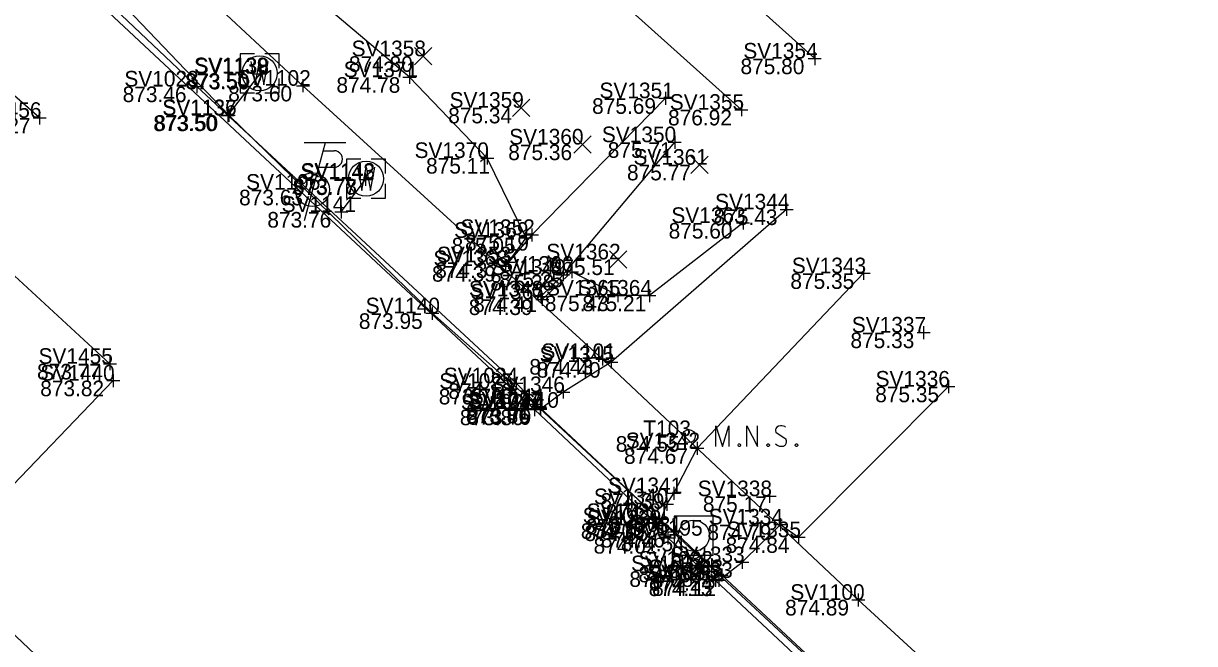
# Model space of a CAD drawing. Extents: x 1480001 to 1480402, y 379235 to 379603.
# Drawn here: x 1480133.3 to 1480223.3, y 379434.1 to 379481.8 of the extents above; entities that cross this region are included whole.
import ezdxf

# ---------------------------------------------------------------- set-up
doc = ezdxf.new("R2010")
doc.units = 0
for name, color, linetype in [('BD_X_Building', 7, 'Continuous'), ('BD_X_Porch_or_Deck', 7, 'Continuous'), ('PM_P_CL_Double_Solid', 7, 'Continuous'), ('PM_X_Lane_Line', 7, 'Continuous'), ('PM_X_Stop_Line', 7, 'Continuous'), ('PV_X_Curb', 7, 'Continuous'), ('PV_X_Driveway', 7, 'Continuous'), ('PV_X_Walk', 7, 'Continuous'), ('SG_X_Poles', 7, 'Continuous'), ('SV_P_Control_Cells_Set', 7, 'Continuous'), ('SV_X_Random_Point', 7, 'Continuous'), ('SV_X_Shot_Marker', 7, 'Continuous'), ('SV_X_Text_Elevation', 7, 'Continuous'), ('SV_X_Text_Name', 7, 'Continuous'), ('SV_X_Top_of_Bank', 7, 'Continuous'), ('UT_X_Misc_Cells', 7, 'Continuous'), ('UT_X_Water', 7, 'Continuous'), ('UT_X_Water_Cells', 7, 'Continuous')]:
    doc.layers.add(name, color=color, linetype=linetype)

msp = doc.modelspace()

# ---------------------------------------------------------------- linework, layer by layer
at = {"layer": 'BD_X_Building'}
msp.add_line((1480194.12, 379479.058), (1480181.546, 379490.377), dxfattribs=at)
at = {"layer": 'BD_X_Porch_or_Deck'}
msp.add_line((1480188.477, 379475.121), (1480178.147, 379484.41), dxfattribs=at)
at = {"layer": 'PM_P_CL_Double_Solid'}
msp.add_lwpolyline([(1480030.312, 379558.368), (1480048.994, 379540.544), (1480068.184, 379522.458), (1480086.697, 379505.162), (1480104.247, 379488.61), (1480122.276, 379471.896), (1480139.96, 379455.601)], dxfattribs=at)
at = {"layer": 'PM_X_Lane_Line'}
msp.add_line((1480134.548, 379474.499), (1480127.117, 379481.028), dxfattribs=at)
at = {"layer": 'PM_X_Stop_Line'}
msp.add_line((1480127.237, 379440.807), (1480140.21, 379454.309), dxfattribs=at)
at = {"layer": 'PV_X_Curb'}
for points in [[(1480042.95, 379573.802), (1480051.182, 379566.018), (1480067.383, 379550.834), (1480087.586, 379531.809), (1480105.067, 379515.41), (1480105.589, 379514.887), (1480115.079, 379506.297), (1480116.303, 379505.052), (1480118.53, 379502.967), (1480120.902, 379500.821), (1480138.714, 379483.703), (1480170.84, 379453.681), (1480172.574, 379452.083), (1480181.867, 379443.345), (1480182.839, 379442.217), (1480185.607, 379439.661), (1480186.493, 379438.955), (1480206.919, 379419.855)], [(1480043.308, 379574.086), (1480051.435, 379566.534), (1480067.64, 379551.083), (1480087.827, 379532.141), (1480105.189, 379515.816), (1480105.937, 379515.205), (1480115.287, 379506.588), (1480116.588, 379505.377), (1480116.999, 379505.563), (1480121.373, 379501.34), (1480121.053, 379501.135), (1480146.64, 379476.909), (1480171.177, 379454.102), (1480173.021, 379452.229), (1480182.175, 379443.675), (1480183.379, 379442.683), (1480186.184, 379440.013), (1480186.975, 379439.363), (1480207.407, 379420.301)], [(1480135.19, 379432.332), (1480118.45, 379448.16), (1480110.152, 379455.954), (1480109.273, 379456.61), (1480100.92, 379464.722), (1480096.044, 379469.27), (1480093.779, 379471.437), (1480091.422, 379473.761), (1480089.145, 379475.876), (1480069.411, 379494.504), (1480056.455, 379506.379), (1480055.435, 379507.417), (1480042.302, 379520.019), (1480041.64, 379520.833), (1480030.984, 379530.729), (1480016.059, 379544.67)]]:
    msp.add_lwpolyline(points, dxfattribs=at)
at = {"layer": 'PV_X_Driveway'}
for points in [[(1480191.959, 379467.465), (1480178.482, 379455.738), (1480174.79, 379453.425), (1480173.043, 379452.118)], [(1480182.148, 379443.183), (1480182.758, 379444.811), (1480183.297, 379445.659), (1480185.095, 379449.116), (1480197.866, 379462.558)], [(1480186.755, 379438.964), (1480188.543, 379440.354), (1480191.477, 379443.253), (1480192.87, 379442.276), (1480204.388, 379453.849)]]:
    msp.add_lwpolyline(points, dxfattribs=at)
at = {"layer": 'PV_X_Walk'}
for points in [[(1480235.613, 379401.335), (1480215.341, 379421.047), (1480197.466, 379437.463), (1480177.803, 379455.97), (1480154.79, 379476.967), (1480132.747, 379497.48), (1480113.376, 379516.728), (1480110.754, 379519.04), (1480109.877, 379518.336), (1480091.944, 379535.267), (1480093.027, 379536.619), (1480090.219, 379539.243), (1480090.463, 379539.725), (1480084.681, 379544.882), (1480083.843, 379544.144), (1480066.818, 379560.524), (1480045.662, 379580.046)], [(1480182.64, 379476.009), (1480172.384, 379465.5), (1480170.586, 379463.4)], [(1480173.058, 379460.776), (1480174.782, 379462.443), (1480183.362, 379472.63)]]:
    msp.add_lwpolyline(points, dxfattribs=at)
at = {"layer": 'SG_X_Poles'}
msp.add_lwpolyline([(1480183.322, 379440.895), (1480186.322, 379440.895), (1480186.322, 379443.895), (1480183.322, 379443.895)], close=True, dxfattribs=at)
msp.add_circle((1480184.822, 379442.395), 1.2, dxfattribs=at)
at = {"layer": 'SV_P_Control_Cells_Set'}
for points in [[(1480186.529, 379449.245), (1480186.529, 379450.845), (1480187.036, 379449.245), (1480187.521, 379450.845), (1480187.521, 379449.245)], [(1480188.899, 379449.245), (1480188.899, 379450.845), (1480189.726, 379449.245), (1480189.726, 379450.845)], [(1480191.876, 379450.732), (1480191.854, 379450.757), (1480191.82, 379450.782), (1480191.721, 379450.82), (1480191.6, 379450.845), (1480191.512, 379450.845), (1480191.479, 379450.845), (1480191.335, 379450.808), (1480191.214, 379450.732), (1480191.137, 379450.631), (1480191.115, 379450.53), (1480191.115, 379450.455), (1480191.137, 379450.354), (1480191.225, 379450.266), (1480191.832, 379449.888), (1480191.887, 379449.838), (1480191.909, 379449.787), (1480191.931, 379449.712), (1480191.931, 379449.636), (1480191.92, 379449.56), (1480191.909, 379449.51), (1480191.887, 379449.447), (1480191.865, 379449.397), (1480191.842, 379449.359), (1480191.809, 379449.321), (1480191.776, 379449.296), (1480191.732, 379449.271), (1480191.699, 379449.258), (1480191.6, 379449.245), (1480191.446, 379449.245), (1480191.347, 379449.271), (1480191.203, 379449.359), (1480191.115, 379449.434)], [(1480188.293, 379449.46), (1480188.348, 379449.46), (1480188.381, 379449.434), (1480188.414, 379449.384), (1480188.414, 379449.321), (1480188.381, 379449.271), (1480188.348, 379449.245), (1480188.293, 379449.245), (1480188.26, 379449.271), (1480188.227, 379449.321), (1480188.227, 379449.384), (1480188.26, 379449.434), (1480188.293, 379449.46)], [(1480190.509, 379449.46), (1480190.564, 379449.46), (1480190.597, 379449.434), (1480190.63, 379449.384), (1480190.63, 379449.321), (1480190.597, 379449.271), (1480190.564, 379449.245), (1480190.509, 379449.245), (1480190.476, 379449.271), (1480190.443, 379449.321), (1480190.443, 379449.384), (1480190.476, 379449.434), (1480190.509, 379449.46)], [(1480192.691, 379449.46), (1480192.746, 379449.46), (1480192.78, 379449.434), (1480192.812, 379449.384), (1480192.812, 379449.321), (1480192.78, 379449.271), (1480192.746, 379449.245), (1480192.691, 379449.245), (1480192.658, 379449.271), (1480192.625, 379449.321), (1480192.625, 379449.384), (1480192.658, 379449.434), (1480192.691, 379449.46)]]:
    msp.add_lwpolyline(points, dxfattribs=at)
msp.add_circle((1480184.44, 379450.045), 0.497, dxfattribs=at)
at = {"layer": 'SV_X_Random_Point'}
for p, q in [((1480163.369, 379478.57), (1480164.703, 379479.905)), ((1480163.369, 379479.905), (1480164.703, 379478.57)), ((1480170.896, 379474.613), (1480172.23, 379475.948)), ((1480170.896, 379475.948), (1480172.23, 379474.613)), ((1480175.594, 379471.785), (1480176.928, 379473.12)), ((1480175.594, 379473.12), (1480176.928, 379471.785)), ((1480184.606, 379470.232), (1480185.94, 379471.567)), ((1480184.606, 379471.567), (1480185.94, 379470.232)), ((1480178.334, 379462.956), (1480179.668, 379464.291)), ((1480178.334, 379464.291), (1480179.668, 379462.956))]:
    msp.add_line(p, q, dxfattribs=at)
at = {"layer": 'SV_X_Shot_Marker'}
for p, q in [((1480194.12, 379479.558), (1480194.12, 379478.558)), ((1480151.509, 379478.389), (1480151.509, 379477.389)), ((1480193.62, 379479.058), (1480194.62, 379479.058)), ((1480194.12, 379479.058), (1480194.12, 379479.058)), ((1480151.009, 379477.889), (1480152.009, 379477.889)), ((1480151.509, 379477.889), (1480151.509, 379477.889)), ((1480154.79, 379477.467), (1480154.79, 379476.467)), ((1480162.466, 379477.627), (1480163.466, 379477.627)), ((1480162.966, 379478.127), (1480162.966, 379477.127)), ((1480162.966, 379477.627), (1480162.966, 379477.627)), ((1480146.14, 379476.909), (1480147.14, 379476.909)), ((1480146.64, 379477.409), (1480146.64, 379476.409)), ((1480146.64, 379476.909), (1480146.64, 379476.909)), ((1480154.29, 379476.967), (1480155.29, 379476.967)), ((1480154.79, 379476.967), (1480154.79, 379476.967)), ((1480182.14, 379476.009), (1480183.14, 379476.009)), ((1480182.64, 379476.509), (1480182.64, 379475.509)), ((1480182.64, 379476.009), (1480182.64, 379476.009)), ((1480134.548, 379474.999), (1480134.548, 379473.999)), ((1480149.013, 379475.18), (1480149.013, 379474.18)), ((1480149.088, 379475.208), (1480149.088, 379474.208)), ((1480187.977, 379475.121), (1480188.977, 379475.121)), ((1480188.477, 379475.621), (1480188.477, 379474.621)), ((1480188.477, 379475.121), (1480188.477, 379475.121)), ((1480134.048, 379474.499), (1480135.048, 379474.499)), ((1480134.548, 379474.499), (1480134.548, 379474.499)), ((1480148.513, 379474.68), (1480149.513, 379474.68)), ((1480148.588, 379474.708), (1480149.588, 379474.708)), ((1480149.013, 379474.68), (1480149.013, 379474.68)), ((1480149.088, 379474.708), (1480149.088, 379474.708)), ((1480183.362, 379473.13), (1480183.362, 379472.13)), ((1480182.862, 379472.63), (1480183.862, 379472.63)), ((1480183.362, 379472.63), (1480183.362, 379472.63)), ((1480168.447, 379471.416), (1480169.447, 379471.416)), ((1480168.947, 379471.916), (1480168.947, 379470.916)), ((1480168.947, 379471.416), (1480168.947, 379471.416)), ((1480159.603, 379470.273), (1480159.603, 379469.273)), ((1480159.103, 379469.773), (1480160.103, 379469.773)), ((1480159.603, 379469.773), (1480159.603, 379469.773)), ((1480157.731, 379467.768), (1480157.731, 379466.768)), ((1480191.959, 379467.965), (1480191.959, 379466.965)), ((1480157.231, 379467.268), (1480158.231, 379467.268)), ((1480157.731, 379467.268), (1480157.731, 379467.268)), ((1480188.616, 379466.924), (1480188.616, 379465.924)), ((1480191.459, 379467.465), (1480192.459, 379467.465)), ((1480191.959, 379467.465), (1480191.959, 379467.465)), ((1480171.936, 379465.783), (1480171.936, 379464.783)), ((1480172.384, 379466), (1480172.384, 379465)), ((1480188.116, 379466.424), (1480189.116, 379466.424)), ((1480188.616, 379466.424), (1480188.616, 379466.424)), ((1480171.436, 379465.283), (1480172.436, 379465.283)), ((1480171.884, 379465.5), (1480172.884, 379465.5)), ((1480171.936, 379465.283), (1480171.936, 379465.283)), ((1480172.384, 379465.5), (1480172.384, 379465.5)), ((1480169.845, 379463.114), (1480170.845, 379463.114)), ((1480170.086, 379463.4), (1480171.086, 379463.4)), ((1480170.345, 379463.614), (1480170.345, 379462.614)), ((1480170.345, 379463.114), (1480170.345, 379463.114)), ((1480170.586, 379463.9), (1480170.586, 379462.9)), ((1480170.586, 379463.4), (1480170.586, 379463.4)), ((1480175.453, 379463.18), (1480175.453, 379462.18)), ((1480197.866, 379463.058), (1480197.866, 379462.058)), ((1480174.282, 379462.443), (1480175.282, 379462.443)), ((1480174.782, 379462.943), (1480174.782, 379461.943)), ((1480174.782, 379462.443), (1480174.782, 379462.443)), ((1480174.953, 379462.68), (1480175.953, 379462.68)), ((1480175.453, 379462.68), (1480175.453, 379462.68)), ((1480197.366, 379462.558), (1480198.366, 379462.558)), ((1480197.866, 379462.558), (1480197.866, 379462.558)), ((1480173.058, 379461.276), (1480173.058, 379460.276)), ((1480178.989, 379461.344), (1480178.989, 379460.344)), ((1480181.409, 379461.341), (1480181.409, 379460.341)), ((1480172.558, 379460.776), (1480173.558, 379460.776)), ((1480172.677, 379460.55), (1480173.677, 379460.55)), ((1480173.058, 379460.776), (1480173.058, 379460.776)), ((1480173.177, 379461.05), (1480173.177, 379460.05)), ((1480173.177, 379460.55), (1480173.177, 379460.55)), ((1480178.489, 379460.844), (1480179.489, 379460.844)), ((1480178.989, 379460.844), (1480178.989, 379460.844)), ((1480180.909, 379460.841), (1480181.909, 379460.841)), ((1480181.409, 379460.841), (1480181.409, 379460.841)), ((1480164.226, 379459.482), (1480165.226, 379459.482)), ((1480164.726, 379459.982), (1480164.726, 379458.982)), ((1480164.726, 379459.482), (1480164.726, 379459.482)), ((1480201.985, 379458.005), (1480202.985, 379458.005)), ((1480202.485, 379458.505), (1480202.485, 379457.505)), ((1480202.485, 379458.005), (1480202.485, 379458.005)), ((1480139.96, 379456.101), (1480139.96, 379455.101)), ((1480177.303, 379455.97), (1480178.303, 379455.97)), ((1480177.803, 379456.47), (1480177.803, 379455.47)), ((1480177.803, 379455.97), (1480177.803, 379455.97)), ((1480178.482, 379456.238), (1480178.482, 379455.238)), ((1480139.46, 379455.601), (1480140.46, 379455.601)), ((1480139.96, 379455.601), (1480139.96, 379455.601)), ((1480177.982, 379455.738), (1480178.982, 379455.738)), ((1480178.482, 379455.738), (1480178.482, 379455.738)), ((1480139.71, 379454.309), (1480140.71, 379454.309)), ((1480140.21, 379454.809), (1480140.21, 379453.809)), ((1480140.21, 379454.309), (1480140.21, 379454.309)), ((1480170.677, 379454.102), (1480171.677, 379454.102)), ((1480170.84, 379454.181), (1480170.84, 379453.181)), ((1480171.177, 379454.602), (1480171.177, 379453.602)), ((1480171.177, 379454.102), (1480171.177, 379454.102)), ((1480204.388, 379454.349), (1480204.388, 379453.349)), ((1480170.34, 379453.681), (1480171.34, 379453.681)), ((1480170.84, 379453.681), (1480170.84, 379453.681)), ((1480174.29, 379453.425), (1480175.29, 379453.425)), ((1480174.79, 379453.925), (1480174.79, 379452.925)), ((1480174.79, 379453.425), (1480174.79, 379453.425)), ((1480203.888, 379453.849), (1480204.888, 379453.849)), ((1480204.388, 379453.849), (1480204.388, 379453.849)), ((1480172.122, 379452.503), (1480173.122, 379452.503)), ((1480172.574, 379452.583), (1480172.574, 379451.583)), ((1480172.622, 379453.003), (1480172.622, 379452.003)), ((1480172.622, 379452.503), (1480172.622, 379452.503)), ((1480173.021, 379452.729), (1480173.021, 379451.729)), ((1480173.043, 379452.618), (1480173.043, 379451.618)), ((1480172.074, 379452.083), (1480173.074, 379452.083)), ((1480172.521, 379452.229), (1480173.521, 379452.229)), ((1480172.543, 379452.118), (1480173.543, 379452.118)), ((1480172.574, 379452.083), (1480172.574, 379452.083)), ((1480173.021, 379452.229), (1480173.021, 379452.229)), ((1480173.043, 379452.118), (1480173.043, 379452.118)), ((1480185.095, 379449.616), (1480185.095, 379448.616)), ((1480184.595, 379449.116), (1480185.595, 379449.116)), ((1480185.095, 379449.116), (1480185.095, 379449.116)), ((1480183.297, 379446.159), (1480183.297, 379445.159)), ((1480182.758, 379445.311), (1480182.758, 379444.311)), ((1480182.797, 379445.659), (1480183.797, 379445.659)), ((1480183.297, 379445.659), (1480183.297, 379445.659)), ((1480190.152, 379445.428), (1480191.152, 379445.428)), ((1480190.652, 379445.928), (1480190.652, 379444.928)), ((1480190.652, 379445.428), (1480190.652, 379445.428)), ((1480182.175, 379444.175), (1480182.175, 379443.175)), ((1480182.258, 379444.811), (1480183.258, 379444.811)), ((1480182.758, 379444.811), (1480182.758, 379444.811)), ((1480181.367, 379443.345), (1480182.367, 379443.345)), ((1480181.675, 379443.675), (1480182.675, 379443.675)), ((1480181.867, 379443.845), (1480181.867, 379442.845)), ((1480181.867, 379443.345), (1480181.867, 379443.345)), ((1480182.148, 379443.683), (1480182.148, 379442.683)), ((1480182.175, 379443.675), (1480182.175, 379443.675)), ((1480190.977, 379443.253), (1480191.977, 379443.253)), ((1480191.477, 379443.753), (1480191.477, 379442.753)), ((1480191.477, 379443.253), (1480191.477, 379443.253)), ((1480181.648, 379443.183), (1480182.648, 379443.183)), ((1480182.148, 379443.183), (1480182.148, 379443.183)), ((1480182.839, 379442.717), (1480182.839, 379441.717)), ((1480182.879, 379442.683), (1480183.879, 379442.683)), ((1480183.379, 379443.183), (1480183.379, 379442.183)), ((1480183.379, 379442.683), (1480183.379, 379442.683)), ((1480192.87, 379442.776), (1480192.87, 379441.776)), ((1480182.339, 379442.217), (1480183.339, 379442.217)), ((1480182.839, 379442.217), (1480182.839, 379442.217)), ((1480192.37, 379442.276), (1480193.37, 379442.276)), ((1480192.87, 379442.276), (1480192.87, 379442.276)), ((1480188.543, 379440.854), (1480188.543, 379439.854)), ((1480185.107, 379439.661), (1480186.107, 379439.661)), ((1480185.607, 379440.161), (1480185.607, 379439.161)), ((1480185.607, 379439.661), (1480185.607, 379439.661)), ((1480185.684, 379440.013), (1480186.684, 379440.013)), ((1480186.184, 379440.513), (1480186.184, 379439.513)), ((1480186.184, 379440.013), (1480186.184, 379440.013)), ((1480186.975, 379439.863), (1480186.975, 379438.863)), ((1480188.043, 379440.354), (1480189.043, 379440.354)), ((1480188.543, 379440.354), (1480188.543, 379440.354)), ((1480185.993, 379438.955), (1480186.993, 379438.955)), ((1480186.255, 379438.964), (1480187.255, 379438.964)), ((1480186.475, 379439.363), (1480187.475, 379439.363)), ((1480186.493, 379439.455), (1480186.493, 379438.455)), ((1480186.493, 379438.955), (1480186.493, 379438.955)), ((1480186.755, 379439.464), (1480186.755, 379438.464)), ((1480186.755, 379438.964), (1480186.755, 379438.964)), ((1480186.975, 379439.363), (1480186.975, 379439.363)), ((1480197.466, 379437.963), (1480197.466, 379436.963)), ((1480196.966, 379437.463), (1480197.966, 379437.463)), ((1480197.466, 379437.463), (1480197.466, 379437.463))]:
    msp.add_line(p, q, dxfattribs=at)
at = {"layer": 'SV_X_Top_of_Bank'}
for points in [[(1480170.345, 379463.114), (1480171.936, 379465.283), (1480168.947, 379471.416), (1480162.966, 379477.627), (1480148.764, 379489.638), (1480146.649, 379490.926), (1480144.483, 379489.446), (1480143.212, 379488.463)], [(1480188.616, 379466.424), (1480181.409, 379460.841), (1480178.989, 379460.844), (1480175.453, 379462.68), (1480173.177, 379460.55)]]:
    msp.add_lwpolyline(points, dxfattribs=at)
at = {"layer": 'UT_X_Misc_Cells'}
for p, q in [((1480156.486, 379472.579), (1480154.88, 379466.579)), ((1480158.086, 379472.579), (1480154.886, 379472.579)), ((1480156.326, 379471.979), (1480157.176, 379471.979)), ((1480155.985, 379470.704), (1480157.176, 379470.704))]:
    msp.add_line(p, q, dxfattribs=at)
msp.add_circle((1480155.523, 379468.979), 1.3, dxfattribs=at)
msp.add_arc((1480157.189, 379471.341), 0.638, 268.8767, 91.1233, dxfattribs=at)
at = {"layer": 'UT_X_Water'}
for p, q in [((1480149.013, 379474.68), (1480151.509, 379477.889)), ((1480157.731, 379467.268), (1480159.603, 379469.773))]:
    msp.add_line(p, q, dxfattribs=at)
msp.add_lwpolyline([(1480049.152, 379568.017), (1480068.611, 379550.193), (1480086.403, 379533.424), (1480090.024, 379530.079), (1480102.295, 379519.134), (1480111.734, 379511.473), (1480120.332, 379509.136), (1480127.535, 379501.668), (1480127.911, 379496.395), (1480140.166, 379484.084), (1480149.088, 379474.708), (1480164.726, 379459.482), (1480172.622, 379452.503), (1480197.813, 379429.111), (1480212.628, 379415.684), (1480231.592, 379398.237)], dxfattribs=at)
at = {"layer": 'UT_X_Water_Cells'}
for p, q in [((1480151.46, 379477.928), (1480151.46, 379477.928)), ((1480159.64, 379469.823), (1480159.64, 379469.823))]:
    msp.add_line(p, q, dxfattribs=at)
for points in [[(1480151.06, 379479.428), (1480149.96, 379479.428), (1480149.96, 379478.328)], [(1480152.96, 379478.328), (1480152.96, 379479.428), (1480151.86, 379479.428)], [(1480150.793, 379478.828), (1480151.127, 379477.028), (1480151.46, 379478.828), (1480151.793, 379477.028), (1480152.127, 379478.828)], [(1480149.96, 379477.528), (1480149.96, 379476.428), (1480151.06, 379476.428)], [(1480151.86, 379476.428), (1480152.96, 379476.428), (1480152.96, 379477.528)], [(1480159.24, 379471.323), (1480158.14, 379471.323), (1480158.14, 379470.223)], [(1480161.14, 379470.223), (1480161.14, 379471.323), (1480160.04, 379471.323)], [(1480158.973, 379470.723), (1480159.307, 379468.923), (1480159.64, 379470.723), (1480159.973, 379468.923), (1480160.307, 379470.723)], [(1480158.14, 379469.423), (1480158.14, 379468.323), (1480159.24, 379468.323)], [(1480160.04, 379468.323), (1480161.14, 379468.323), (1480161.14, 379469.423)]]:
    msp.add_lwpolyline(points, dxfattribs=at)
for centre in [(1480151.46, 379477.928), (1480159.64, 379469.823)]:
    msp.add_circle(centre, 1.35, dxfattribs=at)

# ---------------------------------------------------------------- texts
at = {"layer": 'SV_X_Text_Elevation'}
for s, p in [('874.80', (1480158.32, 379478.037)), ('875.80', (1480188.413, 379477.858)), ('873.50', (1480145.734, 379476.728)), ('873.50', (1480145.783, 379476.689)), ('874.78', (1480157.363, 379476.427)), ('873.46', (1480140.933, 379475.709)), ('873.60', (1480149.045, 379475.767)), ('875.69', (1480177.009, 379474.809)), ('875.34', (1480165.951, 379474.08)), ('876.92', (1480182.846, 379473.921)), ('873.27', (1480128.945, 379473.299)), ('873.50', (1480143.287, 379473.48)), ('873.50', (1480143.362, 379473.508)), ('875.36', (1480170.564, 379471.253)), ('875.71', (1480178.212, 379471.43)), ('875.11', (1480164.251, 379470.216)), ('875.77', (1480179.689, 379469.699)), ('873.77', (1480154, 379468.573)), ('873.78', (1480154.028, 379468.623)), ('873.63', (1480149.882, 379467.779)), ('873.76', (1480152.053, 379466.068)), ('875.43', (1480186.347, 379466.265)), ('875.60', (1480182.89, 379465.224)), ('875.05', (1480166.22, 379464.083)), ('875.19', (1480167.245, 379464.3)), ('874.39', (1480164.704, 379461.914)), ('874.37', (1480164.955, 379462.2)), ('875.51', (1480173.832, 379462.423)), ('875.28', (1480169.189, 379461.243)), ('875.25', (1480169.869, 379461.48)), ('875.35', (1480192.244, 379461.358)), ('874.39', (1480167.536, 379459.35)), ('874.41', (1480167.87, 379459.576)), ('875.43', (1480173.377, 379459.644)), ('875.21', (1480176.259, 379459.641)), ('873.95', (1480159.085, 379458.282)), ('875.33', (1480196.863, 379456.805)), ('874.43', (1480172.182, 379454.77)), ('873.77', (1480134.357, 379454.401)), ('874.40', (1480172.757, 379454.538)), ('873.82', (1480134.598, 379453.109)), ('874.16', (1480165.962, 379452.902)), ('873.79', (1480165.228, 379452.481)), ('874.10', (1480169.547, 379452.225)), ('875.35', (1480198.766, 379452.649)), ('873.86', (1480167.324, 379451.029)), ('874.01', (1480167.33, 379451.303)), ('873.80', (1480166.848, 379450.883)), ('873.79', (1480167.431, 379450.918)), ('874.55', (1480178.827, 379448.846)), ('874.67', (1480179.464, 379447.916)), ('874.39', (1480177.656, 379444.459)), ('875.17', (1480185.522, 379444.228)), ('874.11', (1480178.053, 379443.611)), ('874.05', (1480176.142, 379442.145)), ('873.97', (1480176.534, 379442.475)), ('874.79', (1480185.874, 379442.053)), ('874.05', (1480176.423, 379441.983)), ('874.46', (1480177.682, 379441.483)), ('874.54', (1480179.219, 379441.195)), ('874.02', (1480177.123, 379441.017)), ('874.84', (1480187.267, 379441.076)), ('874.08', (1480179.872, 379438.461)), ('874.53', (1480180.572, 379438.813)), ('874.33', (1480182.912, 379439.154)), ('874.13', (1480181.354, 379437.755)), ('874.24', (1480181.391, 379438.163)), ('874.12', (1480181.625, 379437.764)), ('874.89', (1480191.844, 379436.263))]:
    msp.add_text(s, height=1.2, dxfattribs=at).set_placement(p)
at = {"layer": 'SV_X_Text_Name'}
for s, p in [('SV1358', (1480158.528, 379479.237)), ('SV1354', (1480188.631, 379479.058)), ('SV1139', (1480146.425, 379477.928)), ('SV1138', (1480146.474, 379477.889)), ('SV1371', (1480157.921, 379477.627)), ('SV1023', (1480141.066, 379476.909)), ('SV1102', (1480149.68, 379476.967)), ('SV1351', (1480177.576, 379476.009)), ('SV1456', (1480128.984, 379474.499)), ('SV1136', (1480143.987, 379474.708)), ('SV1137', (1480143.988, 379474.68)), ('SV1359', (1480166.055, 379475.28)), ('SV1355', (1480182.979, 379475.121)), ('SV1350', (1480177.76, 379472.63)), ('SV1360', (1480170.64, 379472.453)), ('SV1370', (1480163.364, 379471.416)), ('SV1361', (1480180.19, 379470.899)), ('SV1142', (1480154.597, 379469.773)), ('SV1143', (1480154.624, 379469.823)), ('SV1196', (1480150.422, 379468.979)), ('SV1141', (1480153.149, 379467.268)), ('SV1344', (1480186.461, 379467.465)), ('SV1363', (1480183.099, 379466.424)), ('SV1352', (1480166.895, 379465.5)), ('SV1369', (1480166.409, 379465.283)), ('SV1362', (1480173.493, 379463.623)), ('SV1368', (1480164.818, 379463.114)), ('SV1353', (1480165.088, 379463.4)), ('SV1349', (1480169.265, 379462.443)), ('SV1366', (1480169.86, 379462.68)), ('SV1343', (1480192.358, 379462.558)), ('SV1348', (1480167.541, 379460.776)), ('SV1367', (1480167.66, 379460.55)), ('SV1365', (1480173.472, 379460.844)), ('SV1364', (1480175.901, 379460.841)), ('SV1140', (1480159.606, 379459.482)), ('SV1337', (1480196.968, 379458.005)), ('SV1455', (1480134.471, 379455.601)), ('SV1345', (1480172.974, 379455.738)), ('SV1101', (1480173.117, 379455.97)), ('SV1440', (1480134.608, 379454.309)), ('SV1024', (1480165.613, 379454.102)), ('SV1336', (1480198.795, 379453.849)), ('SV1025', (1480165.266, 379453.681)), ('SV1346', (1480169.207, 379453.425)), ('SV1026', (1480166.925, 379452.083)), ('SV1027', (1480167.447, 379452.229)), ('SV1347', (1480167.535, 379452.118)), ('SV1144', (1480167.616, 379452.503)), ('T103', (1480180.944, 379450.046)), ('SV1342', (1480179.597, 379449.116)), ('SV1341', (1480178.223, 379445.659)), ('SV1340', (1480177.146, 379444.811)), ('SV1338', (1480185.125, 379445.428)), ('SV1029', (1480176.284, 379443.345)), ('SV1028', (1480176.592, 379443.675)), ('SV1339', (1480176.621, 379443.183)), ('SV1334', (1480185.969, 379443.253)), ('SV1030', (1480177.123, 379442.217)), ('SV1031', (1480178.201, 379442.683)), ('SV1195', (1480179.797, 379442.395)), ('SV1335', (1480187.353, 379442.276)), ('SV1333', (1480183.026, 379440.354)), ('SV1034', (1480180.005, 379439.661)), ('SV1032', (1480180.582, 379440.013)), ('SV1033', (1480181.363, 379439.363)), ('SV1035', (1480180.881, 379438.955)), ('SV1332', (1480181.247, 379438.964)), ('SV1100', (1480192.242, 379437.463))]:
    msp.add_text(s, height=1.2, dxfattribs=at).set_placement(p)

doc.saveas('drawing.dxf')
